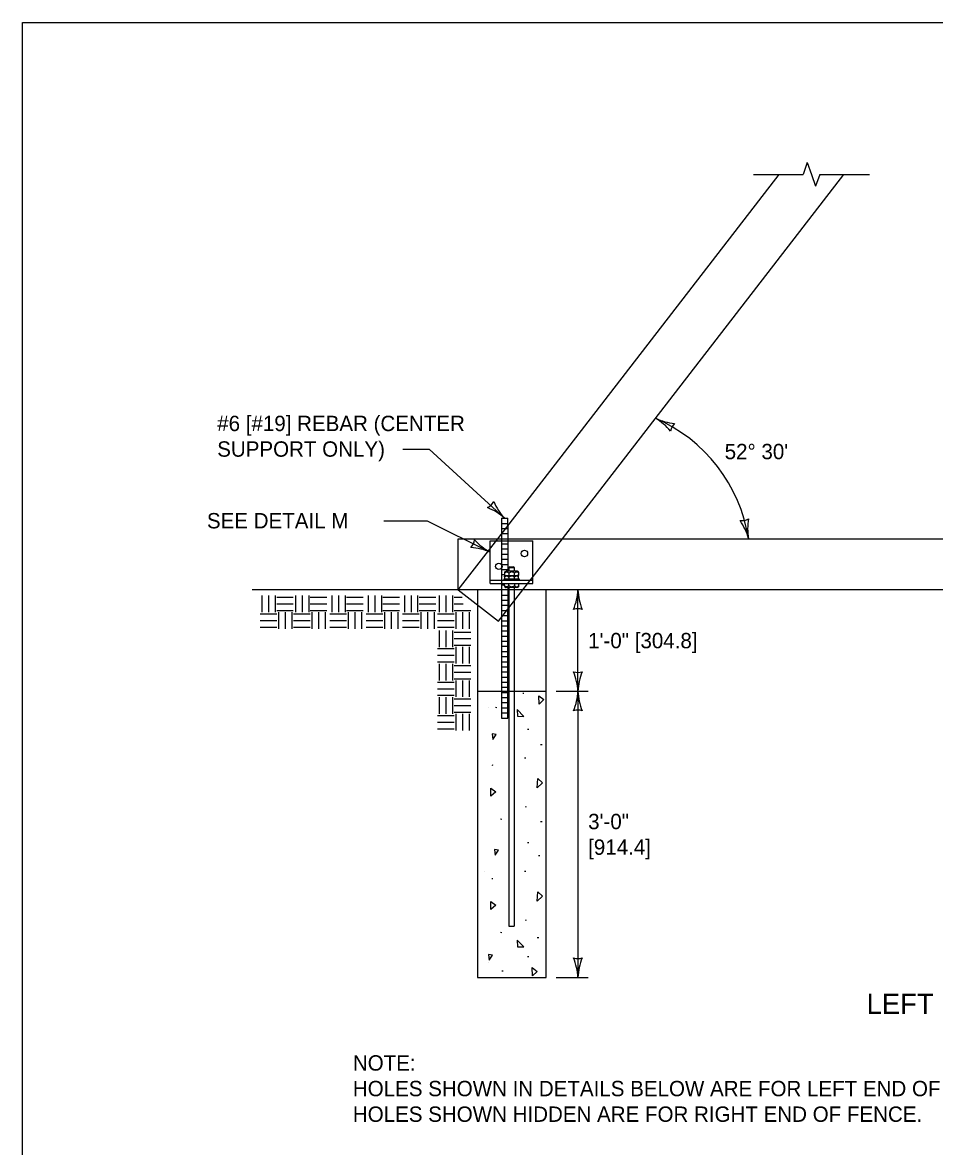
# Model space of a CAD drawing. Extents: x 49991.4 to 50021, y 49987.6 to 50011.4.
# Drawn here: x 49999.384 to 50002.947, y 49994.611 to 49998.999 of the extents above; entities that cross this region are included whole.
import ezdxf

# ---------------------------------------------------------------- set-up
doc = ezdxf.new("R2010")
doc.units = 0
for name, color, linetype in [('Level 1', 7, 'Continuous'), ('Level 2', 7, 'Continuous'), ('Level 3', 7, 'Continuous'), ('Level 4', 7, 'Continuous'), ('Level 6', 7, 'Continuous')]:
    doc.layers.add(name, color=color, linetype=linetype)

msp = doc.modelspace()

# ---------------------------------------------------------------- linework, layer by layer
at = {"layer": 'Level 1'}
for p, q in [((50001.2402, 49996.9838), (50002.3397, 49998.4062)), ((50001.4929, 49996.9838), (50002.5924, 49998.4062)), ((50001.2546, 49997.0636), (50001.2546, 49997.0024)), ((50001.2546, 49997.0636), (50001.2796, 49997.0636)), ((50001.2546, 49997.0436), (50001.2796, 49997.0436)), ((50001.2796, 49997.0348), (50001.2796, 49997.0636)), ((50001.2546, 49997.0236), (50001.271, 49997.0236)), ((50001.2546, 49997.0036), (50001.2555, 49997.0036)), ((50001.0856, 49996.7838), (50001.0856, 49996.9838)), ((50001.0856, 49996.9838), (50004.9525, 49996.9838)), ((50001.2113, 49996.8091), (50001.2113, 49996.9758)), ((50001.2113, 49996.9758), (50001.378, 49996.9758)), ((50001.378, 49996.8091), (50001.378, 49996.9758)), ((50001.2843, 49996.8707), (50001.3051, 49996.8707)), ((50001.2843, 49996.8707), (50001.2843, 49996.8564)), ((50001.2876, 49996.874), (50001.3018, 49996.874)), ((50001.3051, 49996.8707), (50001.3051, 49996.8564)), ((50001.2113, 49996.8217), (50001.378, 49996.8217)), ((50001.2671, 49996.8345), (50001.2671, 49996.8251)), ((50001.2675, 49996.8502), (50001.2675, 49996.8406)), ((50001.2675, 49996.8406), (50001.3225, 49996.8406)), ((50001.3163, 49996.8564), (50001.2737, 49996.8564)), ((50001.2834, 49996.8329), (50001.2834, 49996.8251)), ((50001.2838, 49996.8486), (50001.2838, 49996.8406)), ((50001.3059, 49996.8251), (50001.3059, 49996.8334)), ((50001.3063, 49996.8406), (50001.3063, 49996.8492)), ((50001.3221, 49996.8251), (50001.3221, 49996.8345)), ((50001.3225, 49996.8406), (50001.3225, 49996.8502)), ((50004.9525, 49996.7838), (50000.2807, 49996.7838)), ((50001.0856, 49996.7838), (50001.2439, 49996.6614)), ((50001.2113, 49996.8091), (50001.378, 49996.8091)), ((50001.2439, 49996.6614), (50001.3384, 49996.7838)), ((50001.2672, 49996.7996), (50001.2672, 49996.8091)), ((50001.316, 49996.7934), (50001.2733, 49996.7934)), ((50001.2835, 49996.8014), (50001.2835, 49996.8091)), ((50001.2843, 49996.7934), (50001.2843, 49995.471)), ((50001.3051, 49996.7934), (50001.3051, 49995.471)), ((50001.306, 49996.8091), (50001.306, 49996.8007)), ((50001.3222, 49996.8091), (50001.3222, 49996.7996)), ((50000.3191, 49996.7613), (50000.3191, 49996.6965)), ((50000.345, 49996.7613), (50000.345, 49996.6965)), ((50000.371, 49996.7613), (50000.371, 49996.6965)), ((50000.377, 49996.7553), (50000.4418, 49996.7553)), ((50000.377, 49996.7294), (50000.4418, 49996.7294)), ((50000.45, 49996.7613), (50000.45, 49996.6965)), ((50000.4759, 49996.7613), (50000.4759, 49996.6965)), ((50000.5019, 49996.7613), (50000.5019, 49996.6965)), ((50000.5079, 49996.7553), (50000.5727, 49996.7553)), ((50000.5079, 49996.7294), (50000.5727, 49996.7294)), ((50000.5919, 49996.7613), (50000.5919, 49996.6965)), ((50000.6178, 49996.7613), (50000.6178, 49996.6965)), ((50000.6438, 49996.7613), (50000.6438, 49996.6965)), ((50000.6498, 49996.7553), (50000.7146, 49996.7553)), ((50000.6498, 49996.7294), (50000.7146, 49996.7294)), ((50000.7338, 49996.7613), (50000.7338, 49996.6965)), ((50000.7597, 49996.7613), (50000.7597, 49996.6965)), ((50000.7857, 49996.7613), (50000.7857, 49996.6965)), ((50000.7917, 49996.7553), (50000.8565, 49996.7553)), ((50000.7917, 49996.7294), (50000.8565, 49996.7294)), ((50000.8757, 49996.7613), (50000.8757, 49996.6965)), ((50000.9016, 49996.7613), (50000.9016, 49996.6965)), ((50000.9276, 49996.7613), (50000.9276, 49996.6965)), ((50000.9336, 49996.7553), (50000.9984, 49996.7553)), ((50000.9336, 49996.7294), (50000.9984, 49996.7294)), ((50001.0121, 49996.7613), (50001.0121, 49996.6965)), ((50001.038, 49996.7613), (50001.038, 49996.6965)), ((50001.064, 49996.7613), (50001.064, 49996.6965)), ((50001.07, 49996.7553), (50001.1012, 49996.7553)), ((50001.07, 49996.7294), (50001.1053, 49996.7294)), ((50000.3121, 49996.6905), (50000.377, 49996.6905)), ((50000.377, 49996.7034), (50000.4418, 49996.7034)), ((50000.3835, 49996.6969), (50000.3835, 49996.6321)), ((50000.4094, 49996.6969), (50000.4094, 49996.6321)), ((50000.4354, 49996.6969), (50000.4354, 49996.6321)), ((50000.443, 49996.6905), (50000.5079, 49996.6905)), ((50000.5079, 49996.7034), (50000.5727, 49996.7034)), ((50000.5144, 49996.6969), (50000.5144, 49996.6321)), ((50000.5403, 49996.6969), (50000.5403, 49996.6321)), ((50000.5663, 49996.6969), (50000.5663, 49996.6321)), ((50000.5849, 49996.6905), (50000.6498, 49996.6905)), ((50000.6498, 49996.7034), (50000.7146, 49996.7034)), ((50000.6563, 49996.6969), (50000.6563, 49996.6321)), ((50000.6822, 49996.6969), (50000.6822, 49996.6321)), ((50000.7082, 49996.6969), (50000.7082, 49996.6321)), ((50000.7268, 49996.6905), (50000.7917, 49996.6905)), ((50000.7917, 49996.7034), (50000.8565, 49996.7034)), ((50000.7982, 49996.6969), (50000.7982, 49996.6321)), ((50000.8241, 49996.6969), (50000.8241, 49996.6321)), ((50000.8501, 49996.6969), (50000.8501, 49996.6321)), ((50000.8687, 49996.6905), (50000.9336, 49996.6905)), ((50000.9336, 49996.7034), (50000.9984, 49996.7034)), ((50000.9401, 49996.6969), (50000.9401, 49996.6321)), ((50000.966, 49996.6969), (50000.966, 49996.6321)), ((50000.992, 49996.6969), (50000.992, 49996.6321)), ((50001.0051, 49996.6905), (50001.07, 49996.6905)), ((50001.07, 49996.7034), (50001.1348, 49996.7034)), ((50001.0765, 49996.6969), (50001.0765, 49996.6321)), ((50001.1024, 49996.6969), (50001.1024, 49996.6321)), ((50001.1284, 49996.6969), (50001.1284, 49996.6321)), ((50001.261, 49996.6836), (50001.2796, 49996.6836)), ((50001.2765, 49996.7036), (50001.2796, 49996.7036)), ((50001.2796, 49996.388), (50001.2796, 49996.7076)), ((50000.3121, 49996.6645), (50000.377, 49996.6645)), ((50000.3121, 49996.6386), (50000.377, 49996.6386)), ((50000.443, 49996.6645), (50000.5079, 49996.6645)), ((50000.443, 49996.6386), (50000.5079, 49996.6386)), ((50000.5849, 49996.6645), (50000.6498, 49996.6645)), ((50000.5849, 49996.6386), (50000.6498, 49996.6386)), ((50000.7268, 49996.6645), (50000.7917, 49996.6645)), ((50000.7268, 49996.6386), (50000.7917, 49996.6386)), ((50000.8687, 49996.6645), (50000.9336, 49996.6645)), ((50000.8687, 49996.6386), (50000.9336, 49996.6386)), ((50001.0051, 49996.6645), (50001.07, 49996.6645)), ((50001.0051, 49996.6386), (50001.07, 49996.6386)), ((50001.2546, 49996.6753), (50001.2546, 49996.388)), ((50001.2546, 49996.6636), (50001.2796, 49996.6636)), ((50001.2546, 49996.6436), (50001.2796, 49996.6436)), ((50001.0121, 49996.6254), (50001.0121, 49996.5606)), ((50001.038, 49996.6254), (50001.038, 49996.5606)), ((50001.064, 49996.6254), (50001.064, 49996.5606)), ((50001.07, 49996.6194), (50001.1348, 49996.6194)), ((50001.2546, 49996.6236), (50001.2796, 49996.6236)), ((50001.2546, 49996.6036), (50001.2796, 49996.6036)), ((50001.0051, 49996.5546), (50001.07, 49996.5546)), ((50001.07, 49996.5935), (50001.1348, 49996.5935)), ((50001.07, 49996.5675), (50001.1348, 49996.5675)), ((50001.0765, 49996.561), (50001.0765, 49996.4962)), ((50001.1024, 49996.561), (50001.1024, 49996.4962)), ((50001.1284, 49996.561), (50001.1284, 49996.4962)), ((50001.2546, 49996.5836), (50001.2796, 49996.5836)), ((50001.2546, 49996.5636), (50001.2796, 49996.5636)), ((50001.0051, 49996.5286), (50001.07, 49996.5286)), ((50001.2546, 49996.5436), (50001.2796, 49996.5436)), ((50001.2546, 49996.5236), (50001.2796, 49996.5236)), ((50001.0051, 49996.5027), (50001.07, 49996.5027)), ((50001.0121, 49996.4949), (50001.0121, 49996.4301)), ((50001.038, 49996.4949), (50001.038, 49996.4301)), ((50001.064, 49996.4949), (50001.064, 49996.4301)), ((50001.07, 49996.4889), (50001.1348, 49996.4889)), ((50001.07, 49996.463), (50001.1348, 49996.463)), ((50001.2546, 49996.5036), (50001.2796, 49996.5036)), ((50001.2546, 49996.4836), (50001.2796, 49996.4836)), ((50001.2546, 49996.4636), (50001.2796, 49996.4636)), ((50001.0051, 49996.4241), (50001.07, 49996.4241)), ((50001.07, 49996.437), (50001.1348, 49996.437)), ((50001.0765, 49996.4305), (50001.0765, 49996.3657)), ((50001.1024, 49996.4305), (50001.1024, 49996.3657)), ((50001.1284, 49996.4305), (50001.1284, 49996.3657)), ((50001.2546, 49996.4436), (50001.2796, 49996.4436)), ((50001.2546, 49996.4236), (50001.2796, 49996.4236)), ((50001.0051, 49996.3981), (50001.07, 49996.3981)), ((50001.162, 49996.388), (50001.4292, 49996.388)), ((50001.162, 49996.388), (50001.162, 49995.271)), ((50001.2546, 49996.4036), (50001.2796, 49996.4036)), ((50001.3379, 49996.3802), (50001.3429, 49996.3802)), ((50001.4292, 49995.271), (50001.4292, 49996.388)), ((50001.0051, 49996.3722), (50001.07, 49996.3722)), ((50001.0121, 49996.3644), (50001.0121, 49996.2996)), ((50001.038, 49996.3644), (50001.038, 49996.2996)), ((50001.064, 49996.3644), (50001.064, 49996.2996)), ((50001.07, 49996.3584), (50001.1348, 49996.3584)), ((50001.07, 49996.3325), (50001.1348, 49996.3325)), ((50001.0051, 49996.2936), (50001.07, 49996.2936)), ((50001.07, 49996.3065), (50001.1348, 49996.3065)), ((50001.0765, 49996.3), (50001.0765, 49996.2352)), ((50001.1024, 49996.3), (50001.1024, 49996.2352)), ((50001.1284, 49996.3), (50001.1284, 49996.2352)), ((50001.2057, 49996.3259), (50001.2057, 49996.3259)), ((50001.2313, 49996.3259), (50001.2369, 49996.3246)), ((50001.0051, 49996.2676), (50001.07, 49996.2676)), ((50001.0051, 49996.2417), (50001.07, 49996.2417)), ((50001.3569, 49996.2404), (50001.3619, 49996.2404)), ((50001.4079, 49996.1798), (50001.4136, 49996.1798)), ((50001.3444, 49996.1279), (50001.3501, 49996.1279)), ((50001.2169, 49996.1004), (50001.2214, 49996.0999)), ((50001.3484, 49995.9368), (50001.3524, 49995.9384)), ((50001.2507, 49995.8902), (50001.2566, 49995.8891)), ((50001.4079, 49995.8799), (50001.4136, 49995.8799)), ((50001.3569, 49995.7978), (50001.3619, 49995.7978)), ((50001.3996, 49995.7468), (50001.4051, 49995.7468)), ((50001.187, 49995.6844), (50001.187, 49995.6844)), ((50001.3444, 49995.6854), (50001.3501, 49995.6854)), ((50001.2169, 49995.6576), (50001.2214, 49995.6576)), ((50001.2843, 49995.471), (50001.3051, 49995.471)), ((50001.3484, 49995.4942), (50001.3524, 49995.4961)), ((50001.2507, 49995.4474), (50001.2566, 49995.4468)), ((50001.3947, 49995.4264), (50001.4006, 49995.4264)), ((50001.2057, 49995.3292), (50001.2057, 49995.3292)), ((50001.3569, 49995.3521), (50001.3619, 49995.3521)), ((50001.2569, 49995.2966), (50001.2623, 49995.2966)), ((50001.162, 49995.271), (50001.4292, 49995.271))]:
    msp.add_line(p, q, dxfattribs=at)
for points in [[(49999.3835, 49998.9992), (50016.7501, 49998.9992), (50016.7501, 49987.7988), (49999.3835, 49987.7988)], [(50001.2637, 49996.8217), (50001.3253, 49996.8217), (50001.3253, 49996.8251), (50001.2637, 49996.8251)], [(50001.4008, 49996.3702), (50001.4209, 49996.3557), (50001.4018, 49996.3382)], [(50001.3177, 49996.2912), (50001.3429, 49996.2899), (50001.3161, 49996.3174)], [(50001.2182, 49996.2224), (50001.2211, 49996.2), (50001.2339, 49996.219)], [(50001.3969, 49996.0478), (50001.4157, 49996.0304), (50001.3946, 49996.0106)], [(50001.2129, 49996.0101), (50001.2331, 49995.9956), (50001.2139, 49995.9781)], [(50001.2277, 49995.7705), (50001.2306, 49995.7482), (50001.2434, 49995.7672)], [(50001.3969, 49995.6054), (50001.4157, 49995.5874), (50001.3946, 49995.5682)], [(50001.2129, 49995.5678), (50001.2331, 49995.5528), (50001.2139, 49995.5358)], [(50001.3177, 49995.3908), (50001.3429, 49995.3896), (50001.3161, 49995.4169)], [(50001.204, 49995.3606), (50001.2069, 49995.3383), (50001.2197, 49995.3573)], [(50001.3747, 49995.3095), (50001.3948, 49995.2945), (50001.3757, 49995.2775)]]:
    msp.add_lwpolyline(points, close=True, dxfattribs=at)
for centre in [(50001.3447, 49996.9258), (50001.2447, 49996.8758)]:
    msp.add_circle(centre, 0.0125, dxfattribs=at)
for centre, radius, start, end in [((50001.2876, 49996.8707), 0.00333, 90, 180), ((50001.3018, 49996.8707), 0.00333, 0, 90), ((50001.275, 49996.8278), 0.00975, 31.3232, 144.3102), ((50001.2754, 49996.8436), 0.00975, 31.3232, 144.5627), ((50001.2949, 49996.8225), 0.0155, 44.7321, 137.9001), ((50001.2953, 49996.8382), 0.0155, 44.7309, 137.9001), ((50001.314, 49996.8283), 0.00956, 31.9567, 147.9066), ((50001.3144, 49996.8441), 0.00956, 32.2386, 147.9066), ((50001.2751, 49996.8063), 0.00975, 215.9408, 329.5156), ((50001.295, 49996.8117), 0.0155, 221.9444, 314.7583), ((50001.3141, 49996.8058), 0.00956, 212.1383, 328.3274)]:
    msp.add_arc(centre, radius, start, end, dxfattribs=at)
for points in [[(50001.2671, 49996.8345), (50001.2671, 49996.8348), (50001.2671, 49996.8351), (50001.2671, 49996.8354), (50001.2672, 49996.8358), (50001.2673, 49996.836), (50001.2673, 49996.8364), (50001.2673, 49996.8366), (50001.2674, 49996.8369), (50001.2675, 49996.8372), (50001.2676, 49996.8374), (50001.2677, 49996.8377), (50001.2678, 49996.8379), (50001.2679, 49996.8381), (50001.2681, 49996.8384), (50001.2682, 49996.8386), (50001.2683, 49996.8388), (50001.2685, 49996.8389), (50001.2687, 49996.8391), (50001.2689, 49996.8393), (50001.269, 49996.8394), (50001.2692, 49996.8396), (50001.2694, 49996.8397), (50001.2697, 49996.8398), (50001.2699, 49996.84), (50001.2701, 49996.8401), (50001.2703, 49996.8402), (50001.2706, 49996.8403), (50001.2709, 49996.8404), (50001.2711, 49996.8404), (50001.2714, 49996.8405), (50001.2717, 49996.8405), (50001.272, 49996.8406), (50001.2723, 49996.8406), (50001.2727, 49996.8406), (50001.2729, 49996.8406), (50001.2733, 49996.8406)], [(50001.2675, 49996.8502), (50001.2675, 49996.8506), (50001.2675, 49996.8509), (50001.2676, 49996.8512), (50001.2676, 49996.8515), (50001.2677, 49996.8518), (50001.2677, 49996.8521), (50001.2677, 49996.8524), (50001.2678, 49996.8526), (50001.2679, 49996.8529), (50001.268, 49996.8532), (50001.2681, 49996.8534), (50001.2682, 49996.8536), (50001.2683, 49996.8539), (50001.2685, 49996.8541), (50001.2686, 49996.8543), (50001.2687, 49996.8545), (50001.2689, 49996.8547), (50001.2691, 49996.8548), (50001.2693, 49996.855), (50001.2695, 49996.8552), (50001.2697, 49996.8553), (50001.2699, 49996.8555), (50001.2701, 49996.8556), (50001.2703, 49996.8557), (50001.2705, 49996.8558), (50001.2707, 49996.8559), (50001.271, 49996.856), (50001.2713, 49996.8561), (50001.2715, 49996.8562), (50001.2719, 49996.8562), (50001.2721, 49996.8563), (50001.2725, 49996.8563), (50001.2727, 49996.8564), (50001.2731, 49996.8564), (50001.2734, 49996.8564), (50001.2737, 49996.8564)], [(50001.3221, 49996.8345), (50001.3221, 49996.8348), (50001.3221, 49996.8351), (50001.3221, 49996.8354), (50001.3221, 49996.8358), (50001.322, 49996.836), (50001.3219, 49996.8364), (50001.3219, 49996.8366), (50001.3218, 49996.8369), (50001.3217, 49996.8372), (50001.3217, 49996.8374), (50001.3215, 49996.8377), (50001.3215, 49996.8379), (50001.3213, 49996.8381), (50001.3212, 49996.8384), (50001.3211, 49996.8386), (50001.3209, 49996.8388), (50001.3207, 49996.8389), (50001.3205, 49996.8391), (50001.3204, 49996.8393), (50001.3202, 49996.8394), (50001.32, 49996.8396), (50001.3198, 49996.8397), (50001.3196, 49996.8398), (50001.3193, 49996.84), (50001.3191, 49996.8401), (50001.3189, 49996.8402), (50001.3187, 49996.8403), (50001.3183, 49996.8404), (50001.3181, 49996.8404), (50001.3178, 49996.8405), (50001.3175, 49996.8405), (50001.3172, 49996.8406), (50001.3169, 49996.8406), (50001.3166, 49996.8406), (50001.3163, 49996.8406), (50001.3159, 49996.8406)], [(50001.3225, 49996.8502), (50001.3225, 49996.8506), (50001.3225, 49996.8509), (50001.3225, 49996.8512), (50001.3225, 49996.8515), (50001.3224, 49996.8518), (50001.3223, 49996.8521), (50001.3223, 49996.8524), (50001.3223, 49996.8526), (50001.3221, 49996.8529), (50001.3221, 49996.8532), (50001.3219, 49996.8534), (50001.3219, 49996.8536), (50001.3217, 49996.8539), (50001.3216, 49996.8541), (50001.3215, 49996.8543), (50001.3213, 49996.8545), (50001.3211, 49996.8547), (50001.321, 49996.8548), (50001.3208, 49996.855), (50001.3207, 49996.8552), (50001.3205, 49996.8553), (50001.3203, 49996.8555), (50001.32, 49996.8556), (50001.3198, 49996.8557), (50001.3195, 49996.8558), (50001.3193, 49996.8559), (50001.3191, 49996.856), (50001.3188, 49996.8561), (50001.3185, 49996.8562), (50001.3183, 49996.8562), (50001.3179, 49996.8563), (50001.3177, 49996.8563), (50001.3173, 49996.8564), (50001.317, 49996.8564), (50001.3167, 49996.8564), (50001.3163, 49996.8564)], [(50001.2672, 49996.7996), (50001.2672, 49996.7993), (50001.2672, 49996.799), (50001.2673, 49996.7986), (50001.2673, 49996.7984), (50001.2673, 49996.798), (50001.2673, 49996.7978), (50001.2674, 49996.7975), (50001.2675, 49996.7972), (50001.2675, 49996.7969), (50001.2677, 49996.7967), (50001.2677, 49996.7964), (50001.2679, 49996.7962), (50001.268, 49996.796), (50001.2681, 49996.7958), (50001.2683, 49996.7956), (50001.2684, 49996.7954), (50001.2685, 49996.7952), (50001.2687, 49996.795), (50001.2689, 49996.7948), (50001.2691, 49996.7947), (50001.2693, 49996.7945), (50001.2695, 49996.7944), (50001.2697, 49996.7942), (50001.2699, 49996.7941), (50001.2701, 49996.794), (50001.2704, 49996.7939), (50001.2707, 49996.7938), (50001.2709, 49996.7938), (50001.2712, 49996.7937), (50001.2715, 49996.7936), (50001.2718, 49996.7936), (50001.2721, 49996.7935), (50001.2724, 49996.7935), (50001.2727, 49996.7935), (50001.2731, 49996.7934), (50001.2733, 49996.7934)], [(50001.3222, 49996.7996), (50001.3222, 49996.7993), (50001.3221, 49996.799), (50001.3221, 49996.7986), (50001.3221, 49996.7984), (50001.3221, 49996.798), (50001.322, 49996.7978), (50001.3219, 49996.7975), (50001.3219, 49996.7972), (50001.3218, 49996.7969), (50001.3217, 49996.7967), (50001.3216, 49996.7964), (50001.3215, 49996.7962), (50001.3214, 49996.796), (50001.3213, 49996.7958), (50001.3211, 49996.7956), (50001.3209, 49996.7954), (50001.3208, 49996.7952), (50001.3207, 49996.795), (50001.3205, 49996.7948), (50001.3203, 49996.7947), (50001.3201, 49996.7945), (50001.3199, 49996.7944), (50001.3197, 49996.7942), (50001.3195, 49996.7941), (50001.3192, 49996.794), (50001.3189, 49996.7939), (50001.3187, 49996.7938), (50001.3185, 49996.7938), (50001.3181, 49996.7937), (50001.3179, 49996.7936), (50001.3176, 49996.7936), (50001.3173, 49996.7935), (50001.317, 49996.7935), (50001.3167, 49996.7935), (50001.3163, 49996.7934), (50001.316, 49996.7934)]]:
    msp.add_spline(points, degree=3, dxfattribs=at)
at = {"layer": 'Level 3'}
for p, q in [((50000.8699, 49997.3338), (50000.9724, 49997.3338)), ((50000.9724, 49997.3338), (50001.2671, 49997.0636)), ((50000.7954, 49997.0539), (50000.9645, 49997.0539)), ((50000.9645, 49997.0539), (50001.2113, 49996.9314)), ((50001.5537, 49996.388), (50001.5537, 49996.7838)), ((50001.4692, 49996.388), (50001.5937, 49996.388)), ((50001.5537, 49996.388), (50001.5537, 49995.271)), ((50001.4692, 49995.271), (50001.5937, 49995.271))]:
    msp.add_line(p, q, dxfattribs=at)
for centre, radius, start, end in [((50001.6122, 49996.8887), 0.6155, 8.8842, 66.6417), ((50001.7458, 49997.2609), 0.2223, 40.0289, 60.2124), ((50001.9532, 49997.6657), 0.233, 245.4002, 264.6501), ((50001.97, 49997.3948), 0.0548, 134.7117, 170.4341), ((50001.1756, 49997.1534), 0.0548, 297.6988, 333.4212), ((50001.4292, 49997.2158), 0.2223, 203.016, 223.1995), ((50001.1124, 49996.8894), 0.233, 48.3873, 67.6372), ((50002.1924, 49997.1089), 0.0548, 264.7007, 300.4231), ((50001.9957, 49996.922), 0.233, 15.3892, 34.6391), ((50002.4391, 49997.0232), 0.2223, 170.0179, 190.2014), ((50001.0957, 49996.9868), 0.0548, 316.5288, 352.2511), ((50001.1211, 49996.7166), 0.233, 67.2172, 86.4671), ((50001.3156, 49997.1278), 0.2223, 221.8459, 242.0295), ((50001.3316, 49996.793), 0.2223, 337.456, 357.6395), ((50001.7864, 49996.7953), 0.233, 182.8273, 202.0772), ((50001.5537, 49996.6556), 0.0548, 72.1388, 107.8612), ((50001.5537, 49996.5162), 0.0548, 252.1388, 287.8612), ((50001.321, 49996.3765), 0.233, 2.8273, 22.0772), ((50001.7758, 49996.3788), 0.2223, 157.456, 177.6395), ((50001.3316, 49996.3972), 0.2223, 337.456, 357.6395), ((50001.7864, 49996.3995), 0.233, 182.8273, 202.0772), ((50001.5537, 49996.2598), 0.0548, 72.1388, 107.8612), ((50001.5537, 49995.3992), 0.0548, 252.1388, 287.8612), ((50001.321, 49995.2595), 0.233, 2.8273, 22.0772), ((50001.7758, 49995.2618), 0.2223, 157.456, 177.6395)]:
    msp.add_arc(centre, radius, start, end, dxfattribs=at)
at = {"layer": 'Level 4'}
for p, q in [((50001.2796, 49997.0348), (50001.2796, 49996.8564)), ((50001.2546, 49997.0024), (50001.2546, 49996.6753)), ((50001.2555, 49997.0036), (50001.2796, 49997.0036)), ((50001.271, 49997.0236), (50001.2796, 49997.0236)), ((50001.0856, 49996.7838), (50001.2402, 49996.9838)), ((50001.2546, 49996.9636), (50001.2796, 49996.9636)), ((50001.3384, 49996.7838), (50001.4929, 49996.9838)), ((50001.2546, 49996.9436), (50001.2796, 49996.9436)), ((50001.2546, 49996.9236), (50001.2796, 49996.9236)), ((50001.2546, 49996.9036), (50001.2796, 49996.9036)), ((50001.2546, 49996.8836), (50001.2796, 49996.8836)), ((50001.2546, 49996.8636), (50001.2796, 49996.8636)), ((50001.2546, 49996.8436), (50001.2675, 49996.8436)), ((50001.162, 49996.7838), (50001.162, 49996.388)), ((50001.2546, 49996.8036), (50001.2672, 49996.8036)), ((50001.2796, 49996.7934), (50001.2796, 49996.7076)), ((50001.4292, 49996.388), (50001.4292, 49996.7838)), ((50001.2546, 49996.7636), (50001.2796, 49996.7636)), ((50001.2546, 49996.7436), (50001.2796, 49996.7436)), ((50001.2546, 49996.7236), (50001.2796, 49996.7236)), ((50001.2546, 49996.7036), (50001.2765, 49996.7036)), ((50001.2546, 49996.6836), (50001.261, 49996.6836)), ((50001.2546, 49996.388), (50001.2546, 49996.2836)), ((50001.2546, 49996.3836), (50001.2796, 49996.3836)), ((50001.2796, 49996.2836), (50001.2796, 49996.388)), ((50001.2546, 49996.3636), (50001.2796, 49996.3636)), ((50001.2546, 49996.3436), (50001.2796, 49996.3436)), ((50001.2546, 49996.3236), (50001.2796, 49996.3236)), ((50001.2546, 49996.3036), (50001.2796, 49996.3036)), ((50001.2546, 49996.2836), (50001.2796, 49996.2836))]:
    msp.add_line(p, q, dxfattribs=at)
at = {"layer": 'Level 6'}
for p, q in [((50002.4498, 49998.4519), (50002.4336, 49998.4062)), ((50002.4498, 49998.4519), (50002.466, 49998.4062)), ((50002.2397, 49998.4062), (50002.4336, 49998.4062)), ((50002.466, 49998.4062), (50002.4822, 49998.3605)), ((50002.4984, 49998.4062), (50002.4822, 49998.3605)), ((50002.4984, 49998.4062), (50002.6924, 49998.4062))]:
    msp.add_line(p, q, dxfattribs=at)

# ---------------------------------------------------------------- texts
at = {"layer": 'Level 2'}
for s, height, p in [('#6 [#19] REBAR (CENTER', 0.06, (50000.1444, 49997.4038)), ('SUPPORT ONLY)', 0.06, (50000.1444, 49997.3038)), ("52° 30'", 0.06, (50002.1271, 49997.294)), ('SEE DETAIL M', 0.06, (50000.1042, 49997.0239)), ('1\'-0" [304.8]', 0.06, (50001.5937, 49996.5559)), ('3\'-0"', 0.06, (50001.5937, 49995.8495)), ('[914.4]', 0.06, (50001.5937, 49995.7495)), ('LEFT END VIEW', 0.08, (50002.682, 49995.1276)), ('NOTE:', 0.06, (50000.6745, 49994.9069)), ('HOLES SHOWN IN DETAILS BELOW ARE FOR LEFT END OF FENCE.', 0.06, (50000.6745, 49994.8069)), ('HOLES SHOWN HIDDEN ARE FOR RIGHT END OF FENCE.', 0.06, (50000.6745, 49994.7069))]:
    msp.add_text(s, height=height, dxfattribs=at).set_placement(p)

doc.saveas('drawing.dxf')
